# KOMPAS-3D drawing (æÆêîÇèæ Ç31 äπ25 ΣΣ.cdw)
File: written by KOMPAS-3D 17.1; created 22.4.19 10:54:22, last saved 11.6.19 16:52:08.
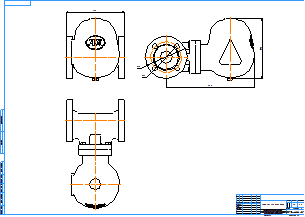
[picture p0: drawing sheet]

Sheet 1: A1, landscape

Title block, sheet 1: name: СТИМАКС А31 Ду25 фф; material: Внимание! Данный продукт является объектом авторского права ООО «Торговый Дом АДЛ». / Запрещается изменение, копирование, распространение / (в том числе путем копирования на другие сайты и ресурсы в Интернете) / или любое иное использование информации и объектов без предварительного / согласия правообладателя (ООО «Торговый Дом АДЛ»).; mass: 12; sheets: 1; organisation: ООО "Торговый дом АДЛ"; sheet format: A1; stored path: \\adlc.lan\data\АДЛ_ПКД\3D-модели\ADL production\Конденсатоотводчики СТИМАКС\Поплавковые\Серия А31\KOMPAS 2D\СТИМАКС А31 Ду25 фф.cdw

Views: Вид 1, Проекционный вид 2, Проекционный вид 3
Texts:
  user
Dimensions and other numbers on the sheet: 160; 241; 115; 164; 85; 1:1; 1; 12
